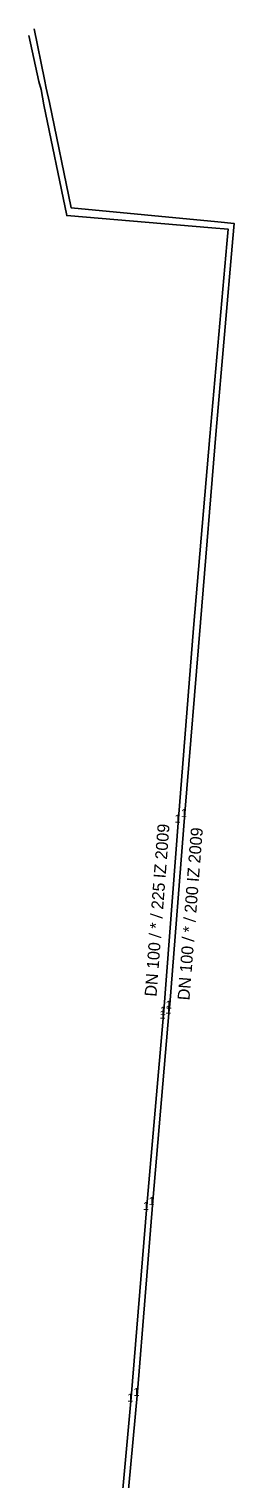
# Model space of a CAD drawing. Extents: x -444513 to -444229, y -1122290 to -1122109.
# Drawn here: x -444409.4 to -444396.6, y -1122199.8 to -1122109.2 of the extents above; entities that cross this region are included whole.
import ezdxf

# ---------------------------------------------------------------- set-up
doc = ezdxf.new("R2010")
doc.units = 0
for name, color, linetype in [('Popis potrubí', 7, 'Continuous'), ('Potrubí tepelného rozvodu - linie', 7, 'Continuous'), ('Vnitřní bod potrubí tepelného rozvodu', 7, 'Continuous')]:
    doc.layers.add(name, color=color, linetype=linetype)

msp = doc.modelspace()

# ---------------------------------------------------------------- linework, layer by layer
at = {"layer": 'Potrubí tepelného rozvodu - linie'}
for points in [[(-444406.39, -1122239.23), (-444406.335, -1122238.447), (-444405.751, -1122231.048), (-444404.876, -1122220.01), (-444404.73, -1122218.71), (-444404.693, -1122218.411), (-444403.746, -1122206.355), (-444402.654, -1122194.385), (-444401.697, -1122182.456), (-444400.66, -1122170.5), (-444400.63, -1122170.19), (-444399.69, -1122158.23), (-444398.717, -1122146.321), (-444397.728, -1122134.324), (-444396.7, -1122122.338), (-444396.62, -1122121.39), (-444397.633, -1122121.292), (-444406.782, -1122120.429), (-444408.144, -1122113.848), (-444408.352, -1122112.951), (-444408.455, -1122112.398), (-444409.1, -1122109.25)], [(-444406.39, -1122239.23), (-444406.335, -1122238.447), (-444405.751, -1122231.048), (-444404.876, -1122220.01), (-444404.73, -1122218.71), (-444404.693, -1122218.411), (-444403.746, -1122206.355), (-444402.654, -1122194.385), (-444401.697, -1122182.456), (-444400.66, -1122170.5), (-444400.63, -1122170.19), (-444399.69, -1122158.23), (-444398.717, -1122146.321), (-444397.728, -1122134.324), (-444396.7, -1122122.338), (-444396.62, -1122121.39), (-444397.633, -1122121.292), (-444406.782, -1122120.429), (-444408.144, -1122113.848), (-444408.352, -1122112.951), (-444408.455, -1122112.398), (-444409.1, -1122109.25)], [(-444409.42, -1122109.65), (-444408.796, -1122112.522), (-444408.663, -1122113.034), (-444408.497, -1122113.998), (-444407.065, -1122120.905), (-444398.006, -1122121.668), (-444396.99, -1122121.75), (-444397.067, -1122122.678), (-444398.12, -1122134.7), (-444399.148, -1122146.673), (-444400.082, -1122158.573), (-444400.998, -1122170.568), (-444401.02, -1122170.81), (-444402.06, -1122182.767), (-444403.036, -1122194.733), (-444404.121, -1122206.653), (-444405.108, -1122218.813), (-444405.13, -1122219.11), (-444405.227, -1122220.378), (-444406.083, -1122231.387), (-444406.7, -1122238.168), (-444406.659, -1122238.935)], [(-444409.42, -1122109.65), (-444408.796, -1122112.522), (-444408.663, -1122113.034), (-444408.497, -1122113.998), (-444407.065, -1122120.905), (-444398.006, -1122121.668), (-444396.99, -1122121.75), (-444397.067, -1122122.678), (-444398.12, -1122134.7), (-444399.148, -1122146.673), (-444400.082, -1122158.573), (-444400.998, -1122170.568), (-444401.02, -1122170.81), (-444402.06, -1122182.767), (-444403.036, -1122194.733), (-444404.121, -1122206.653), (-444405.108, -1122218.813), (-444405.13, -1122219.11), (-444405.227, -1122220.378), (-444406.083, -1122231.387), (-444406.7, -1122238.168), (-444406.659, -1122238.935)]]:
    msp.add_lwpolyline(points, dxfattribs=at)

# ---------------------------------------------------------------- texts
at = {"layer": 'Popis potrubí'}
for s, rotation, p in [('DN 100 / * / 225 IZ 2009', 85.63307, (-444401.46, -1122169.711)), ('DN 100 / * / 225 IZ 2009', 85.63307, (-444401.46, -1122169.711)), ('DN 100 / * / 200 IZ 2009', 85.50606, (-444399.402, -1122169.94)), ('DN 100 / * / 200 IZ 2009', 85.50606, (-444399.402, -1122169.94))]:
    msp.add_text(s, height=0.75, rotation=rotation, dxfattribs=at).set_placement(p)
at = {"layer": 'Vnitřní bod potrubí tepelného rozvodu'}
for p in [(-444400.33, -1122158.82), (-444400.33, -1122158.82), (-444399.94, -1122158.48), (-444399.94, -1122158.48), (-444400.88, -1122170.44), (-444400.88, -1122170.44), (-444401.27, -1122171.06), (-444401.27, -1122171.06), (-444401.25, -1122170.82), (-444401.25, -1122170.82), (-444400.91, -1122170.75), (-444400.91, -1122170.75), (-444402.31, -1122183.02), (-444402.31, -1122183.02), (-444401.95, -1122182.71), (-444401.95, -1122182.71), (-444403.29, -1122194.98), (-444403.29, -1122194.98), (-444402.9, -1122194.63), (-444402.9, -1122194.63)]:
    msp.add_text('1', height=0.5, dxfattribs=at).set_placement(p)

doc.saveas('drawing.dxf')
